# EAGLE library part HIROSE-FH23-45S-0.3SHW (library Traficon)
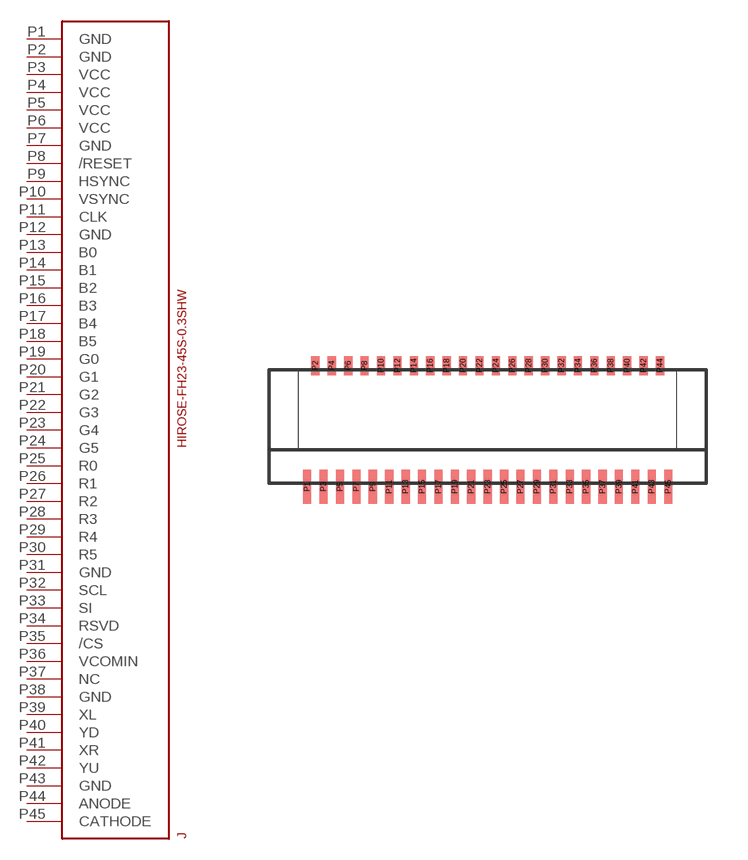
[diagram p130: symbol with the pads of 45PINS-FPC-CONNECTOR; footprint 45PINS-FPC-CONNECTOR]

Designator prefix J

## HIROSE-FH23-45S-0.3SHW  [45PINS-FPC-CONNECTOR]
P1  GND  pwr
P2  GND  pwr
P3  VCC  pwr
P4  VCC  pwr
P5  VCC  pwr
P6  VCC  pwr
P7  GND  pwr
P8  /RESET  in
P9  HSYNC  in
P10  VSYNC  in
P11  CLK  in
P12  GND  pwr
P13  B0  in
P14  B1  in
P15  B2  in
P16  B3  in
P17  B4  in
P18  B5  in
P19  G0  in
P20  G1  in
P21  G2  in
P22  G3  in
P23  G4  in
P24  G5  in
P25  R0  in
P26  R1  in
P27  R2  in
P28  R3  in
P29  R4  in
P30  R5  in
P31  GND  pwr
P32  SCL  in
P33  SI
P34  RSVD  pas
P35  /CS  in
P36  VCOMIN  in
P37  NC  nc
P38  GND  pwr
P39  XL  in
P40  YD  in
P41  XR  in
P42  YU  in
P43  GND  pwr
P44  ANODE  in
P45  CATHODE  in

## Footprint 45PINS-FPC-CONNECTOR (pad centres in mm)
smd 0.3 x 1.25: P1 -6.6,-2.35; P3 -6,-2.35; P5 -5.4,-2.35; P7 -4.8,-2.35; P9 -4.2,-2.35; P11 -3.6,-2.35; P13 -3,-2.35; P15 -2.4,-2.35; P17 -1.8,-2.35; P19 -1.2,-2.35; P21 -0.6,-2.35; P23 0,-2.35; P25 0.6,-2.35; P27 1.2,-2.35; P29 1.8,-2.35; P31 2.4,-2.35; P33 3,-2.35; P35 3.6,-2.35; P37 4.2,-2.35; P39 4.8,-2.35; P41 5.4,-2.35; P43 6,-2.35; P45 6.6,-2.35
smd 0.3 x 0.7: P2 -6.3,2.075; P4 -5.7,2.075; P6 -5.1,2.075; P8 -4.5,2.075; P10 -3.9,2.075; P12 -3.3,2.075; P14 -2.7,2.075; P16 -2.1,2.075; P18 -1.5,2.075; P20 -0.9,2.075; P22 -0.3,2.075; P24 0.3,2.075; P26 0.9,2.075; P28 1.5,2.075; P30 2.1,2.075; P32 2.7,2.075; P34 3.3,2.075; P36 3.9,2.075; P38 4.5,2.075; P40 5.1,2.075; P42 5.7,2.075; P44 6.3,2.075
